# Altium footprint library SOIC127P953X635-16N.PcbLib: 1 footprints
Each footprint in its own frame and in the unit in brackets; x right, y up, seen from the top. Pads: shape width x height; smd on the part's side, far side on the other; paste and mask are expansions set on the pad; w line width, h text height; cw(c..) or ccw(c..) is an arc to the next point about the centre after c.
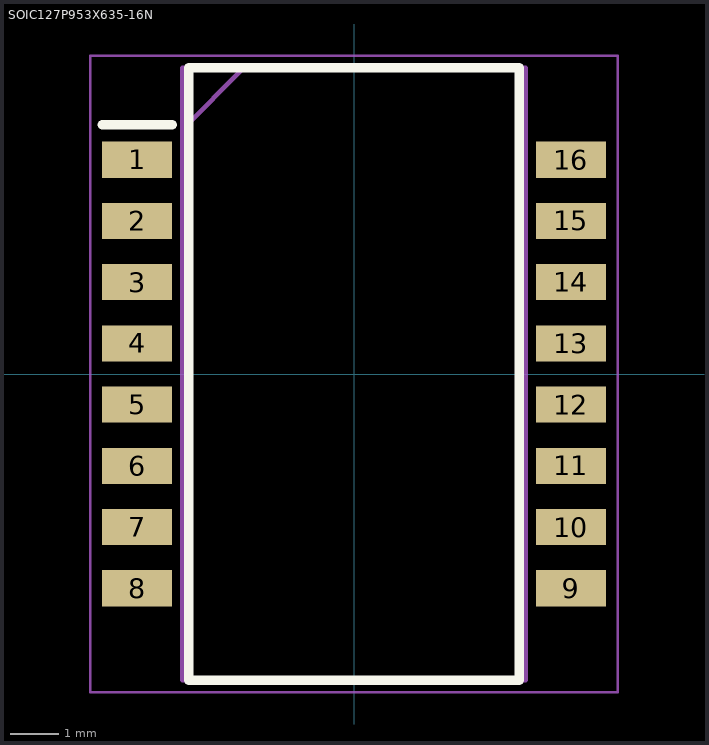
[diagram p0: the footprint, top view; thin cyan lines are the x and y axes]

## SOIC127P953X635-16N [mm]
pads (16):
  rect 1.45x0.75 smd: 1(-4.5,4.445) 2(-4.5,3.175) 3(-4.5,1.905) 4(-4.5,0.635) 5(-4.5,-0.635) 6(-4.5,-1.905) 7(-4.5,-3.175) 8(-4.5,-4.445) 9(4.5,-4.445) 10(4.5,-3.175) 11(4.5,-1.905) 12(4.5,-0.635) 13(4.5,0.635) 14(4.5,1.905) 15(4.5,3.175) 16(4.5,4.445)
Top Overlay:
  lines w0.2: -5.225,5.17 -3.775,5.17 ; -3.425,-6.35 3.425,-6.35 3.425,6.35 -3.425,6.35 -3.425,-6.35
Mechanical 15:
  lines w0.1: -3.555,5.08 -2.285,6.35 ; -3.555,-6.35 3.555,-6.35 3.555,6.35 -3.555,6.35 -3.555,-6.35
Mechanical 20:
  lines w0.05: -5.475,-6.6 5.475,-6.6 5.475,6.6 -5.475,6.6 -5.475,-6.6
